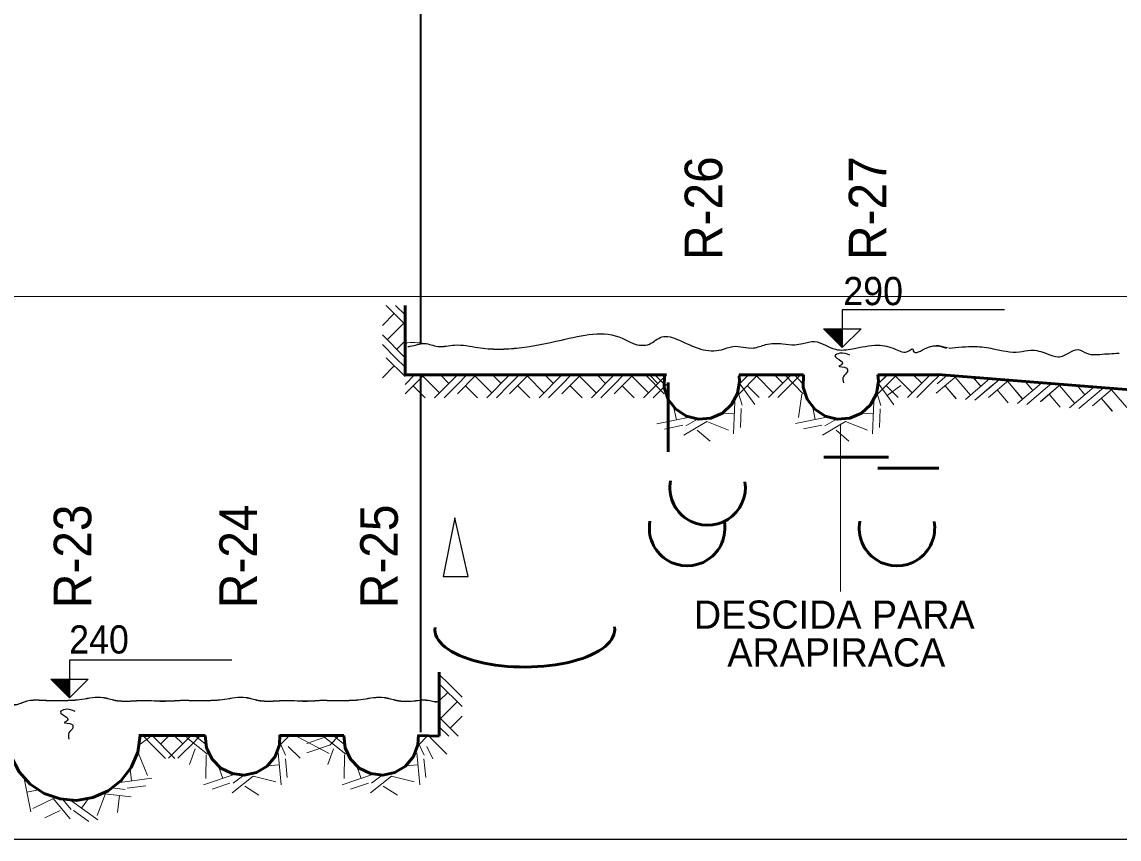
# Model space of a CAD drawing. Extents: x 8458 to 9360, y 19921 to 20366.
# Drawn here: x 9142.5 to 9259.2, y 20102.6 to 20189.5 of the extents above; entities that cross this region are included whole.
import ezdxf

# ---------------------------------------------------------------- set-up
doc = ezdxf.new("R2010")
doc.units = 0
doc.header["$LTSCALE"] = 1.2
doc.layers.add('5', color=7, linetype='Continuous', lineweight=13)

msp = doc.modelspace()

# ---------------------------------------------------------------- linework, layer by layer
at = {"layer": '5', "lineweight": 35}
for p, q in [((9184.9, 20155.21), (9184.9, 20226.35)), ((9183.24, 20159.33), (9183.24, 20151.94)), ((9184.9, 20113.95), (9184.9, 20151.94))]:
    msp.add_line(p, q, dxfattribs=at)
at = {"layer": '5'}
for p, q in [((8509.89, 20160.27), (9341.84, 20160.27)), ((9182.08, 20158.46), (9180.82, 20157.19)), ((9183.24, 20157.31), (9181.22, 20159.33)), ((9183.24, 20158.32), (9182.22, 20159.33)), ((9183.1, 20157.45), (9181.32, 20155.68)), ((9183.24, 20153.77), (9180.82, 20156.19)), ((9182.22, 20153.77), (9180.82, 20155.18)), ((9183.24, 20155.57), (9182.34, 20154.67)), ((9183.24, 20151.76), (9181.22, 20153.77)), ((9183.24, 20152.76), (9182.22, 20153.77)), ((9182.08, 20152.9), (9180.82, 20151.63)), ((9184.25, 20151.94), (9183.24, 20150.93)), ((9185.26, 20151.94), (9183.24, 20149.92)), ((9185.12, 20151.8), (9186.89, 20150.03)), ((9188.8, 20151.94), (9186.38, 20149.52)), ((9187, 20151.94), (9187.9, 20151.04)), ((9189.81, 20151.94), (9188.8, 20150.93)), ((9190.81, 20151.94), (9188.8, 20149.92)), ((9190.68, 20151.8), (9192.45, 20150.03)), ((9194.36, 20151.94), (9191.94, 20149.52)), ((9192.55, 20151.94), (9193.46, 20151.04)), ((9195.37, 20151.94), (9194.36, 20150.93)), ((9196.37, 20151.94), (9194.36, 20149.92)), ((9196.24, 20151.8), (9198.01, 20150.03)), ((9199.92, 20151.94), (9197.5, 20149.52)), ((9198.11, 20151.94), (9199.01, 20151.04)), ((9200.92, 20151.94), (9199.92, 20150.93)), ((9201.93, 20151.94), (9199.92, 20149.92)), ((9201.79, 20151.8), (9203.57, 20150.03)), ((9205.47, 20151.94), (9203.06, 20149.52)), ((9203.67, 20151.94), (9204.57, 20151.04)), ((9206.48, 20151.94), (9205.47, 20150.93)), ((9207.49, 20151.94), (9205.47, 20149.92)), ((9207.35, 20151.8), (9209.12, 20150.03)), ((9211.03, 20151.94), (9208.61, 20149.52)), ((9210.8, 20149.92), (9208.8, 20151.96)), ((9209.23, 20151.94), (9210.13, 20151.04)), ((9210.82, 20150.93), (9209.82, 20151.95)), ((9219.76, 20151.96), (9218.76, 20150.95)), ((9220.78, 20151.96), (9218.76, 20149.94)), ((9220.64, 20151.82), (9222.4, 20150.05)), ((9224.32, 20151.96), (9221.9, 20149.54)), ((9222.52, 20151.96), (9223.42, 20151.06)), ((9225.6, 20149.94), (9223.6, 20151.99)), ((9225.32, 20151.96), (9224.32, 20150.95)), ((9225.6, 20150.95), (9224.62, 20151.98)), ((9234.54, 20151.96), (9233.54, 20150.95)), ((9235.56, 20151.96), (9233.54, 20149.94)), ((9234.55, 20151.96), (9233.54, 20150.95)), ((9235.56, 20151.96), (9233.54, 20149.94)), ((9235.42, 20151.82), (9237.18, 20150.05)), ((9235.42, 20151.82), (9237.19, 20150.05)), ((9239.1, 20151.96), (9236.68, 20149.54)), ((9237.3, 20151.96), (9238.2, 20151.06)), ((9240.11, 20151.96), (9239.1, 20150.95)), ((9241.92, 20151.84), (9239.75, 20149.99)), ((9241.92, 20151.83), (9239.75, 20149.99)), ((9240.92, 20151.92), (9239.83, 20150.99)), ((9240.91, 20151.92), (9239.83, 20151)), ((9241.77, 20151.71), (9243.4, 20149.8)), ((9241.77, 20151.71), (9243.39, 20149.8)), ((9245.45, 20151.55), (9242.85, 20149.33)), ((9245.45, 20151.55), (9242.85, 20149.34)), ((9243.65, 20151.7), (9244.48, 20150.73)), ((9243.66, 20151.69), (9244.48, 20150.72)), ((9246.46, 20151.47), (9245.37, 20150.54)), ((9246.46, 20151.47), (9245.37, 20150.55)), ((9184.11, 20150.79), (9185.38, 20149.52)), ((9188.8, 20150.93), (9187.39, 20149.52)), ((9189.67, 20150.79), (9190.94, 20149.52)), ((9194.36, 20150.93), (9192.95, 20149.52)), ((9195.23, 20150.79), (9196.5, 20149.52)), ((9199.92, 20150.93), (9198.5, 20149.52)), ((9200.79, 20150.79), (9202.06, 20149.52)), ((9205.47, 20150.93), (9204.06, 20149.52)), ((9206.34, 20150.79), (9207.62, 20149.52)), ((9211.03, 20150.93), (9209.62, 20149.52)), ((9218.76, 20151.09), (9220.44, 20148.78)), ((9219.62, 20150.81), (9220.9, 20149.54)), ((9224.32, 20150.95), (9222.9, 20149.54)), ((9233.56, 20151.07), (9235.24, 20148.75)), ((9234.4, 20150.81), (9235.68, 20149.54)), ((9234.41, 20150.81), (9235.68, 20149.54)), ((9234.52, 20149.75), (9235.98, 20150.81)), ((9239.1, 20150.95), (9237.69, 20149.54)), ((9240.69, 20150.79), (9241.85, 20149.42)), ((9240.69, 20150.78), (9241.85, 20149.41)), ((9245.37, 20150.55), (9243.85, 20149.26)), ((9245.37, 20150.54), (9243.85, 20149.25)), ((9247.46, 20151.39), (9245.29, 20149.54)), ((9247.46, 20151.39), (9245.29, 20149.54)), ((9246.23, 20150.34), (9247.39, 20148.97)), ((9246.23, 20150.34), (9247.39, 20148.97)), ((9247.31, 20151.27), (9248.93, 20149.36)), ((9247.31, 20151.26), (9248.94, 20149.35)), ((9250.99, 20151.11), (9248.39, 20148.89)), ((9250.99, 20151.1), (9248.39, 20148.89)), ((9249.19, 20151.25), (9250.02, 20150.28)), ((9249.2, 20151.25), (9250.02, 20150.28)), ((9253, 20150.94), (9250.83, 20149.09)), ((9253, 20150.94), (9250.83, 20149.1)), ((9252, 20151.03), (9250.91, 20150.1)), ((9252, 20151.02), (9250.91, 20150.1)), ((9252.85, 20150.82), (9254.48, 20148.91)), ((9252.85, 20150.81), (9254.48, 20148.91)), ((9256.53, 20150.66), (9253.93, 20148.44)), ((9256.53, 20150.66), (9253.93, 20148.44)), ((9254.73, 20150.81), (9255.56, 20149.83)), ((9254.74, 20150.8), (9255.56, 20149.83)), ((9258.54, 20150.5), (9256.37, 20148.65)), ((9258.54, 20150.49), (9256.37, 20148.65)), ((9257.54, 20150.58), (9256.45, 20149.65)), ((9257.54, 20150.58), (9256.45, 20149.66)), ((9258.39, 20150.37), (9260.02, 20148.46)), ((9258.39, 20150.37), (9260.02, 20148.46)), ((9218.3, 20149.09), (9218.18, 20145.68)), ((9218.66, 20150.08), (9219.08, 20148.71)), ((9225.44, 20149.9), (9225.1, 20147.42)), ((9233.1, 20149.08), (9232.96, 20145.66)), ((9233.44, 20150.06), (9233.86, 20148.69)), ((9250.91, 20150.1), (9249.39, 20148.81)), ((9250.91, 20150.1), (9249.39, 20148.81)), ((9251.77, 20149.9), (9252.93, 20148.52)), ((9251.77, 20149.89), (9252.93, 20148.52)), ((9256.45, 20149.66), (9254.93, 20148.36)), ((9256.45, 20149.65), (9254.93, 20148.36)), ((9257.31, 20149.45), (9258.47, 20148.08)), ((9257.31, 20149.44), (9258.48, 20148.07)), ((9211.84, 20148.42), (9212.1, 20147.17)), ((9218.98, 20148.36), (9218.92, 20146.36)), ((9226.62, 20148.44), (9226.88, 20147.19)), ((9233.78, 20148.34), (9233.7, 20146.34)), ((9213.34, 20147.43), (9210, 20146.74)), ((9215.32, 20147), (9212.88, 20145.54)), ((9214.36, 20147.25), (9213.12, 20146.52)), ((9215.32, 20146.98), (9217.66, 20146.08)), ((9216.98, 20147.87), (9218.26, 20147.82)), ((9228.12, 20147.44), (9224.78, 20146.76)), ((9230.1, 20147), (9227.64, 20145.55)), ((9229.14, 20147.25), (9227.9, 20146.53)), ((9229.57, 20128.91), (9229.57, 20146.75)), ((9230.1, 20146.98), (9232.42, 20146.07)), ((9231.76, 20147.86), (9233.04, 20147.8)), ((9212.8, 20146.59), (9210.84, 20146.18)), ((9214.3, 20146.06), (9215.68, 20144.9)), ((9227.56, 20146.6), (9225.62, 20146.2)), ((9229.08, 20146.07), (9230.46, 20144.9)), ((9186.87, 20120.09), (9187.89, 20119.08)), ((9186.87, 20119.08), (9189.29, 20116.66)), ((9187.89, 20119.08), (9189.29, 20117.67)), ((9186.87, 20117.28), (9187.77, 20118.18)), ((9186.88, 20113.54), (9186.88, 20117.27)), ((9187.01, 20115.4), (9188.79, 20117.17)), ((9186.87, 20115.54), (9188.89, 20113.52)), ((9188.03, 20114.39), (9189.29, 20115.66)), ((9186.87, 20114.53), (9187.89, 20113.52)), ((9154.92, 20112.58), (9156.06, 20113.43)), ((9155.07, 20113.6), (9161.99, 20113.6)), ((9155.32, 20113.58), (9156.32, 20112.57)), ((9156.32, 20113.58), (9158.74, 20111.16)), ((9158.12, 20113.58), (9157.22, 20112.68)), ((9158.68, 20113.59), (9159.58, 20112.69)), ((9160.47, 20113.59), (9159.63, 20112.75)), ((9162.2, 20111.59), (9159.98, 20113.37)), ((9161.48, 20113.59), (9160.48, 20112.58)), ((9162.1, 20112.59), (9160.98, 20113.48)), ((9169.92, 20113.6), (9176.72, 20113.6)), ((9170.94, 20113.59), (9169.92, 20112.58)), ((9171.8, 20113.45), (9175.17, 20111.68)), ((9175.19, 20113.59), (9172.77, 20112.75)), ((9176.93, 20111.59), (9174.71, 20113.37)), ((9176.21, 20113.59), (9175.21, 20112.58)), ((9176.83, 20112.59), (9175.71, 20113.48)), ((9185.67, 20113.59), (9184.65, 20112.58)), ((9185.91, 20113.38), (9187.67, 20111.61)), ((9156.32, 20112.57), (9157.74, 20111.16)), ((9159.63, 20112.75), (9158.05, 20111.17)), ((9159.63, 20111.74), (9159.06, 20111.17)), ((9160.47, 20112.58), (9159.63, 20111.74)), ((9160.9, 20112.19), (9160.3, 20110.5)), ((9169.74, 20111.75), (9170.06, 20108.35)), ((9169.94, 20112.78), (9170.52, 20111.49)), ((9170.8, 20112.44), (9172.06, 20111.17)), ((9175.19, 20112.58), (9172.77, 20111.74)), ((9175.63, 20112.19), (9175.03, 20110.5)), ((9184.47, 20111.75), (9184.79, 20108.35)), ((9184.67, 20112.78), (9185.25, 20111.49)), ((9185.53, 20112.44), (9186.17, 20111.1)), ((9154.88, 20111.68), (9155.82, 20109.35)), ((9162.06, 20111.53), (9162.04, 20109.02)), ((9170.5, 20111.11), (9170.7, 20109.12)), ((9176.79, 20111.53), (9176.77, 20109.02)), ((9185.23, 20111.11), (9185.43, 20109.12)), ((9153.98, 20110.03), (9154.14, 20108.77)), ((9165.04, 20109.43), (9161.8, 20108.33)), ((9163.42, 20110.23), (9163.84, 20109.02)), ((9168.58, 20110.37), (9169.84, 20110.48)), ((9179.77, 20109.43), (9176.53, 20108.33)), ((9178.15, 20110.23), (9178.57, 20109.02)), ((9183.31, 20110.37), (9184.57, 20110.48)), ((9142.74, 20108.83), (9143.42, 20105.47)), ((9152.88, 20108.6), (9156.28, 20109.05)), ((9153.68, 20107.99), (9155.66, 20108.25)), ((9164.6, 20108.52), (9162.7, 20107.88)), ((9167.06, 20109.26), (9164.82, 20107.51)), ((9166.06, 20109.38), (9164.94, 20108.51)), ((9167.06, 20109.27), (9169.48, 20108.67)), ((9179.33, 20108.52), (9177.43, 20107.88)), ((9181.79, 20109.26), (9179.55, 20107.51)), ((9180.79, 20109.38), (9179.67, 20108.51)), ((9181.79, 20109.27), (9184.21, 20108.67)), ((9144.24, 20107.83), (9143, 20107.58)), ((9151.36, 20107.43), (9150.46, 20105.09)), ((9151.26, 20107.39), (9154.08, 20107.06)), ((9152.04, 20108.02), (9153.46, 20107.85)), ((9152.86, 20107.2), (9152.64, 20105.42)), ((9166.18, 20108.21), (9167.68, 20107.23)), ((9180.91, 20108.21), (9182.41, 20107.23)), ((9145.9, 20106.92), (9143.64, 20105.83)), ((9145.78, 20106.91), (9147.6, 20104.73)), ((9146.78, 20106.82), (9147.7, 20105.73)), ((9147.78, 20106.61), (9150.56, 20104.62)), ((9149.56, 20106.91), (9148.82, 20105.87)), ((9146.52, 20105.63), (9144.9, 20104.85)), ((9147.96, 20105.62), (9149.58, 20104.46))]:
    msp.add_line(p, q, dxfattribs=at)
at = {"layer": '5', "lineweight": 53}
for p, q in [((9183.24, 20151.94), (9183.24, 20159.33)), ((9183.24, 20151.94), (9211.04, 20151.94)), ((9183.24, 20151.94), (9211.04, 20151.94)), ((9218.76, 20151.96), (9225.62, 20151.96)), ((9233.54, 20151.96), (9240.02, 20151.96)), ((9233.54, 20151.96), (9240.02, 20151.96)), ((9239.91, 20152), (9317.58, 20145.74)), ((9239.91, 20151.99), (9317.58, 20145.73)), ((9211.22, 20151.14), (9211.22, 20143.75)), ((9227.8, 20143.19), (9234.68, 20143.19)), ((9233.54, 20142.01), (9240.02, 20142.01)), ((9186.87, 20113.52), (9186.87, 20120.34)), ((9154.91, 20113.59), (9159.63, 20113.59)), ((9159.63, 20113.59), (9161.98, 20113.59)), ((9169.92, 20113.59), (9174.37, 20113.59)), ((9172.77, 20113.59), (9176.7, 20113.59)), ((9184.65, 20113.59), (9186.87, 20113.52))]:
    msp.add_line(p, q, dxfattribs=at)
at = {"layer": '5', "lineweight": 25}
for p, q in [((9239.91, 20152), (9317.58, 20145.74)), ((8509.89, 20102.58), (9341.84, 20102.58))]:
    msp.add_line(p, q, dxfattribs=at)
for points in [[(9247.01, 20158.86), (9229.75, 20158.86), (9229.75, 20154.86), (9227.75, 20156.86), (9231.75, 20156.86), (9229.75, 20154.86)], [(9164.79, 20121.59), (9147.53, 20121.59), (9147.53, 20117.59), (9145.53, 20119.59), (9149.53, 20119.59), (9147.53, 20117.59)]]:
    msp.add_lwpolyline(points, dxfattribs=at)
at = {"layer": '5', "lineweight": 35}
for points in [[(9229.71, 20154.97), (9228.03, 20156.74), (9229.61, 20156.73), (9229.65, 20155.16), (9228.35, 20156.58), (9229.49, 20156.59), (9229.53, 20155.47), (9228.67, 20156.45), (9229.37, 20156.46), (9229.45, 20155.73), (9229.05, 20156.34)], [(9229.37, 20156.05), (9229.25, 20156.39), (9228.83, 20156.38), (9229.45, 20155.68)], [(9147.49, 20117.7), (9145.81, 20119.47), (9147.39, 20119.46), (9147.43, 20117.89), (9146.13, 20119.31), (9147.27, 20119.32), (9147.31, 20118.2), (9146.45, 20119.18), (9147.15, 20119.19), (9147.23, 20118.46), (9146.83, 20119.07)], [(9147.15, 20118.78), (9147.03, 20119.12), (9146.61, 20119.11), (9147.23, 20118.41)]]:
    msp.add_lwpolyline(points, dxfattribs=at)
at = {"layer": '5'}
for points in [[(9183.24, 20155.35), (9183.24, 20151.94), (9210.82, 20151.94)], [(9210.82, 20151.94), (9210.8, 20150.61), (9211.22, 20149.34), (9212.04, 20148.29), (9213.16, 20147.55), (9214.44, 20147.23), (9215.78, 20147.34), (9217, 20147.88), (9217.96, 20148.78), (9218.6, 20149.96), (9218.8, 20151.28), (9218.75, 20151.96), (9225.62, 20151.96)], [(9225.62, 20151.96), (9225.6, 20150.63), (9226.02, 20149.36), (9226.82, 20148.3), (9227.94, 20147.56), (9229.22, 20147.23), (9230.56, 20147.33), (9231.78, 20147.86), (9232.76, 20148.77), (9233.38, 20149.94), (9233.6, 20151.26), (9233.54, 20151.96), (9240.41, 20151.96), (9317.58, 20145.74)], [(9140.92, 20113.58), (9140.96, 20113.02), (9141.36, 20111.3), (9142.18, 20109.73), (9143.36, 20108.41), (9144.84, 20107.43), (9146.52, 20106.85), (9148.28, 20106.69), (9150.02, 20106.99), (9151.64, 20107.7), (9153.04, 20108.8), (9154.1, 20110.2), (9154.8, 20111.83), (9155.06, 20113.58)], [(9161.99, 20113.6), (9162.13, 20112.29), (9162.71, 20111.09), (9163.63, 20110.15), (9164.83, 20109.56), (9166.13, 20109.39), (9167.43, 20109.67), (9168.57, 20110.36), (9169.41, 20111.38), (9169.87, 20112.62), (9169.93, 20113.6)], [(9176.71, 20113.58), (9176.85, 20112.27), (9177.43, 20111.07), (9178.35, 20110.13), (9179.55, 20109.54), (9180.85, 20109.37), (9182.15, 20109.65), (9183.29, 20110.34), (9184.13, 20111.36), (9184.59, 20112.6), (9184.65, 20113.59), (9186.87, 20113.52)]]:
    msp.add_lwpolyline(points, dxfattribs=at)
at = {"layer": '5', "lineweight": 53}
for points in [[(9210.82, 20151.94), (9210.8, 20150.61), (9211.22, 20149.34), (9212.04, 20148.29), (9213.16, 20147.55), (9214.44, 20147.23), (9215.78, 20147.34), (9217, 20147.88), (9217.96, 20148.78), (9218.6, 20149.96), (9218.8, 20151.28), (9218.76, 20151.82)], [(9225.62, 20151.96), (9225.6, 20150.63), (9226.02, 20149.36), (9226.82, 20148.3), (9227.94, 20147.56), (9229.22, 20147.23), (9230.56, 20147.33), (9231.78, 20147.86), (9232.76, 20148.77), (9233.38, 20149.94), (9233.6, 20151.26), (9233.54, 20151.96)], [(9155.06, 20113.58), (9154.8, 20111.83), (9154.1, 20110.2), (9153.04, 20108.8), (9151.64, 20107.7), (9150.02, 20106.99), (9148.28, 20106.69), (9146.52, 20106.85), (9144.84, 20107.43), (9143.36, 20108.41), (9142.18, 20109.73), (9141.36, 20111.3), (9140.96, 20113.02), (9140.92, 20113.58)], [(9161.98, 20113.59), (9162.12, 20112.27), (9162.7, 20111.07), (9163.62, 20110.13), (9164.82, 20109.54), (9166.12, 20109.37), (9167.42, 20109.65), (9168.56, 20110.34), (9169.4, 20111.36), (9169.86, 20112.6), (9169.92, 20113.66)], [(9176.71, 20113.59), (9176.85, 20112.27), (9177.43, 20111.07), (9178.35, 20110.13), (9179.55, 20109.54), (9180.85, 20109.37), (9182.15, 20109.65), (9183.29, 20110.34), (9184.13, 20111.36), (9184.59, 20112.6), (9184.65, 20113.66)]]:
    msp.add_lwpolyline(points, dxfattribs=at)
at = {"layer": '5', "lineweight": 25}
msp.add_lwpolyline([(9188.52, 20136.74), (9187.3, 20130.52), (9189.94, 20130.52)], close=True, dxfattribs=at)
at = {"layer": '5', "lineweight": 53}
for centre, start, end in [((9215.42, 20139.97), 169.8463, 8.4206), ((9213.24, 20135.65), 169.5566, 10.4434), ((9235.56, 20135.65), 169.5566, 10.1537)]:
    msp.add_arc(centre, 4.02, start, end, dxfattribs=at)
msp.add_ellipse((9195.97, 20124.85), major_axis=(-9.57, 0), ratio=0.41562, start_param=6.222809, end_param=9.502791, dxfattribs=at)
msp.add_ellipse((9195.97, 20124.85), major_axis=(-9.57, 0), ratio=0.41562, start_param=6.222809, end_param=9.502791, dxfattribs=at)
msp.add_ellipse((9195.97, 20124.85), major_axis=(-9.57, 0), ratio=0.41562, start_param=6.222809, end_param=9.502791, dxfattribs=at)
at = {"layer": '5'}
for points in [[(9241.12, 20154.77), (9238.73, 20154.82), (9237.3, 20154.52), (9237.25, 20154.68), (9236.89, 20154.53), (9235.37, 20154.69), (9233.54, 20155.1), (9230.84, 20154.71), (9229.01, 20154.67), (9226.78, 20155.49), (9225.55, 20155.29), (9224.69, 20155.15), (9223.42, 20155.25), (9221.58, 20155.16), (9220.31, 20154.81), (9218.12, 20154.97), (9216.9, 20154.62), (9214.71, 20154.69), (9212.33, 20155.66), (9210.55, 20155.98), (9209.22, 20155.22), (9207.5, 20155.28), (9206.33, 20155.85), (9199.86, 20155.65), (9190.99, 20154.85), (9188.5, 20155.12), (9186.72, 20154.97), (9185.3, 20155.28), (9183.24, 20155.35)], [(9259.19, 20154.24), (9257.14, 20154.13), (9255.82, 20154.21), (9254.83, 20154.64), (9253.88, 20154.29), (9252.73, 20153.86), (9251.53, 20154.2), (9249.77, 20154.56), (9248.59, 20154.39), (9245.81, 20154.73), (9243.88, 20154.96), (9241.12, 20154.77)], [(9144.69, 20117.35), (9144.31, 20117.37), (9143.04, 20117.28), (9141.77, 20116.88), (9140.5, 20117.04), (9138.82, 20117.04), (9136.78, 20117.16), (9135.36, 20117.57), (9132.46, 20117.74), (9130.89, 20117.59), (9129.46, 20117.09), (9126.92, 20117.46), (9125.13, 20117.01), (9123.31, 20117.58), (9120.81, 20117.29), (9118.88, 20117.09), (9118.01, 20116.94), (9113.03, 20116.82), (9111.81, 20117.33), (9110.54, 20117.34), (9108.45, 20116.99), (9106.01, 20117.36), (9104.69, 20117.47), (9103.67, 20117.37), (9102.09, 20116.87), (9100.42, 20117.74), (9097.67, 20117.45), (9096.8, 20117.71), (9095.38, 20117.56), (9094.36, 20117.52), (9092.53, 20117.02), (9091.26, 20117.28), (9089.89, 20117.49), (9087.85, 20117.09), (9086.83, 20117.5), (9085, 20117.31), (9083.78, 20117.16), (9081.49, 20117.28), (9079.61, 20117.34), (9075.49, 20117.41), (9074.21, 20116.95), (9072.28, 20117.22), (9070.3, 20116.82), (9068.47, 20117.08), (9066.23, 20117.05), (9064.5, 20117.16), (9063.43, 20117.57), (9060.94, 20117.07), (9059.82, 20117.43), (9058.39, 20117.19), (9056.56, 20116.33), (9054.32, 20116.9), (9052.08, 20116.4), (9049.44, 20117.03), (9047.99, 20117.18)], [(9159.64, 20117.36), (9157.14, 20117.27), (9155.97, 20117.32), (9154.24, 20117.28), (9152.41, 20117.34), (9151.09, 20117.65), (9148.85, 20117.46), (9146.86, 20117.32), (9145.23, 20117.33), (9144.69, 20117.36)], [(9174.38, 20117.36), (9172.34, 20117.27), (9171.17, 20117.32), (9169.44, 20117.28), (9167.61, 20117.34), (9166.29, 20117.65), (9164.05, 20117.46), (9162.06, 20117.32), (9160.43, 20117.33), (9159.64, 20117.36)], [(9186.88, 20117.27), (9186.43, 20117.2), (9185.89, 20117.32), (9184.16, 20117.28), (9182.33, 20117.34), (9181.01, 20117.65), (9178.77, 20117.46), (9176.78, 20117.32), (9175.15, 20117.33), (9174.38, 20117.36)]]:
    msp.add_spline(points, degree=3, dxfattribs=at)
at = {"layer": '5', "lineweight": 25}
for points in [[(9183.54, 20154.97), (9183.77, 20154.99), (9185.3, 20155.28), (9186.72, 20154.97), (9188.5, 20155.12), (9190.99, 20154.85), (9199.86, 20155.65), (9206.33, 20155.85), (9207.5, 20155.28), (9209.22, 20155.22), (9210.55, 20155.98), (9212.33, 20155.66), (9214.71, 20154.69), (9216.9, 20154.62), (9218.12, 20154.97), (9220.31, 20154.81), (9221.58, 20155.16), (9223.42, 20155.25), (9224.69, 20155.15), (9225.55, 20155.29), (9226.78, 20155.49), (9229.01, 20154.67), (9230.84, 20154.71), (9233.54, 20155.1), (9235.37, 20154.69), (9236.89, 20154.53), (9237.25, 20154.68), (9237.3, 20154.52), (9238.73, 20154.82), (9240.83, 20154.8)], [(9241.12, 20154.77), (9243.88, 20154.96), (9245.81, 20154.73), (9248.59, 20154.39), (9249.77, 20154.57), (9251.53, 20154.2), (9252.73, 20153.86), (9253.88, 20154.29), (9254.83, 20154.64), (9255.82, 20154.21), (9257.14, 20154.13), (9259.19, 20154.25)], [(9230.55, 20154.04), (9229.47, 20154.24), (9228.97, 20153.98), (9229.63, 20153.42), (9229.77, 20153.18), (9229.37, 20152.86), (9230.23, 20152.66), (9230.29, 20152.3), (9229.87, 20151.76), (9229.87, 20151.1)], [(9047.86, 20117.18), (9049.43, 20117.02), (9052.07, 20116.39), (9054.31, 20116.89), (9056.55, 20116.32), (9058.38, 20117.18), (9059.81, 20117.42), (9060.93, 20117.06), (9063.42, 20117.56), (9064.49, 20117.15), (9066.22, 20117.04), (9068.46, 20117.07), (9070.29, 20116.81), (9072.27, 20117.21), (9074.2, 20116.94), (9075.48, 20117.4), (9079.6, 20117.33), (9081.48, 20117.27), (9083.77, 20117.15), (9084.99, 20117.3), (9086.82, 20117.49), (9087.84, 20117.08), (9089.88, 20117.48), (9091.25, 20117.27), (9092.52, 20117.01), (9094.35, 20117.51), (9095.37, 20117.55), (9096.79, 20117.7), (9097.66, 20117.44), (9100.41, 20117.73), (9102.08, 20116.86), (9103.66, 20117.36), (9104.68, 20117.46), (9106, 20117.35), (9108.44, 20116.98), (9110.53, 20117.33), (9111.8, 20117.32), (9113.02, 20116.81), (9118, 20116.93), (9118.87, 20117.08), (9120.8, 20117.28), (9123.3, 20117.57), (9125.12, 20117), (9126.91, 20117.45), (9129.45, 20117.08), (9130.88, 20117.58), (9132.45, 20117.73), (9135.35, 20117.56), (9136.77, 20117.15), (9138.81, 20117.03), (9140.49, 20117.03), (9141.76, 20116.87), (9143.03, 20117.27), (9144.3, 20117.36), (9144.68, 20117.34)], [(9144.43, 20117.36), (9145.22, 20117.32), (9146.85, 20117.31), (9148.84, 20117.45), (9151.08, 20117.64), (9152.4, 20117.33), (9154.23, 20117.27), (9155.96, 20117.31), (9157.13, 20117.26), (9159.63, 20117.35)], [(9159.63, 20117.35), (9160.42, 20117.32), (9162.05, 20117.31), (9164.04, 20117.45), (9166.28, 20117.64), (9167.6, 20117.33), (9169.43, 20117.27), (9171.16, 20117.31), (9172.33, 20117.26), (9174.39, 20117.35)], [(9174.35, 20117.35), (9175.14, 20117.32), (9176.77, 20117.31), (9178.76, 20117.45), (9181, 20117.64), (9182.32, 20117.33), (9184.15, 20117.27), (9185.88, 20117.31), (9186.42, 20117.19), (9186.75, 20117.2)], [(9148.14, 20116.15), (9147.06, 20116.35), (9146.56, 20116.09), (9147.22, 20115.53), (9147.36, 20115.29), (9146.96, 20114.97), (9147.82, 20114.77), (9147.88, 20114.41), (9147.46, 20113.87), (9147.46, 20113.21)]]:
    msp.add_spline(points, degree=3, dxfattribs=at)

# ---------------------------------------------------------------- texts
at = {"layer": '5', "width": 0.95}
for s, p in [('R-26', (9216.98, 20164.17)), ('R-27', (9234.44, 20164.17)), ('R-23', (9149.85, 20127.14)), ('R-24', (9167.47, 20127.14)), ('R-25', (9182.46, 20127.14))]:
    msp.add_text(s, height=4, rotation=90, dxfattribs=at).set_placement(p)
for s, p in [('290', (9229.85, 20159.36)), ('240', (9147.49, 20122.31))]:
    msp.add_text(s, height=3, dxfattribs=at).set_placement(p)
at = {"layer": '5'}
for s, p in [('DESCIDA PARA', (9213.96, 20124.95)), ('ARAPIRACA', (9217.52, 20120.93))]:
    msp.add_text(s, height=3, dxfattribs=at).set_placement(p)

doc.saveas('drawing.dxf')
